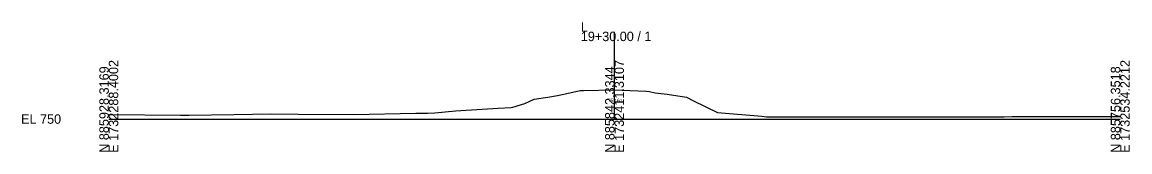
# Model space of a CAD drawing. Extents: x -173 to 6803, y -2990 to 11029.
# Drawn here: x -25.7 to 302.8, y 10990.3 to 11028.7 of the extents above; entities that cross this region are included whole.
import ezdxf

# ---------------------------------------------------------------- set-up
doc = ezdxf.new("R2010")
doc.units = 0
for name, color, linetype in [('Default', 7, 'Continuous'), ('Exist Cross Section Cell', 7, 'Continuous'), ('Exist XS Center Line Elevation Label', 7, 'Continuous'), ('Exist XS Ground Line', 7, 'Continuous')]:
    doc.layers.add(name, color=color, linetype=linetype)

msp = doc.modelspace()

# ---------------------------------------------------------------- linework, layer by layer
at = {"layer": 'Exist Cross Section Cell'}
for p, q in [((150, 11000), (150, 11025.86)), ((0, 11000), (150, 11000)), ((150, 11000), (300, 11000))]:
    msp.add_line(p, q, dxfattribs=at)
at = {"layer": 'Exist XS Ground Line'}
msp.add_lwpolyline([(0, 11001.3), (21.29, 11001.13), (23.72, 11001.11), (37.09, 11001.34), (48.13, 11001.56), (56.18, 11001.48), (72.54, 11001.32), (91.08, 11001.72), (94.53, 11001.78), (96.66, 11001.85), (102.83, 11002.43), (115.45, 11003.22), (119.35, 11003.46), (119.85, 11003.51), (123.42, 11004.62), (126.13, 11005.9), (130.24, 11006.44), (133.1, 11006.93), (136.71, 11007.72), (139.81, 11008.4), (140.8, 11008.42), (149.83, 11008.62), (159.45, 11008.21), (160.36, 11008.18), (162.06, 11007.79), (165.61, 11007.34), (171.33, 11006.44), (173.44, 11005.4), (180.51, 11001.97), (193.68, 11000.82), (194.38, 11000.76), (195.06, 11000.7), (195.75, 11000.7), (218.99, 11000.65), (230.67, 11000.66), (238.14, 11000.66), (243.38, 11000.62), (252.51, 11000.62), (265.52, 11000.7), (267.8, 11000.72), (281.23, 11000.74), (292.21, 11000.8), (295.59, 11000.78), (300, 11000.72)], dxfattribs=at)

# ---------------------------------------------------------------- texts
at = {"layer": 'Default'}
msp.add_text('-', height=0.0001, dxfattribs=at).set_placement((0, 11000))
at = {"layer": 'Exist Cross Section Cell'}
for s, p in [('19+30.00 / 1', (140, 11023.06)), ('L', (140, 11025.86)), ('EL 750', (-26, 10998.6))]:
    msp.add_text(s, height=2.8, dxfattribs=at).set_placement(p)
for s, p in [('E 1732288.4002', (2.8, 10990)), ('E 1732411.3107', (152.8, 10990)), ('E 1732534.2212', (302.8, 10990)), ('N 885928.3169', (0, 10990)), ('N 885842.3344', (150, 10990)), ('N 885756.3518', (300, 10990))]:
    msp.add_text(s, height=2.8, rotation=90, dxfattribs=at).set_placement(p)
at = {"layer": 'Exist XS Center Line Elevation Label'}
msp.add_text('758.61', height=1, rotation=360, dxfattribs=at).set_placement((148.1, 11005.01))

doc.saveas('drawing.dxf')
